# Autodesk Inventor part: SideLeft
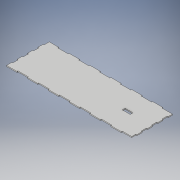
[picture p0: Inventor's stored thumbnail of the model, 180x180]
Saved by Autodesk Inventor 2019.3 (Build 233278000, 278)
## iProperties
Created: 2020-02
Part Number: SideLeft
Material: Generic
Document SubType Name: Modeling
Designer: KrystynWikoff
Density: 1 g/cm^3
Appearance: Default
Author: KrystynWikoff
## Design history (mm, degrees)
sketch "Sketch1"
  geometry: L1 (0, 0)-(304.8, 0); L2 (304.8, 0)-(304.8, -101.6); L3 (304.8, -101.6)-(0, -101.6); L4 (0, -101.6)-(0, 0)
  constraints: 8 end point, 2 parallel, 1 horizontal, 1 perpendicular
  dimensions: "d0" = 304.8 distance of L1.start L1.end; "d1" = 101.6 distance of L3.end L1.start
extrude "Extrusion1" new body sketch "Sketch1" distance "d2" = 2.3622; taper "d3" = 0 deg
sketch "Sketch2"
  geometry: L1 (-69.977, 46.99)-(-50.8, 46.99); L2 (-50.8, 46.99)-(-50.8, 53.848); L3 (-50.8, 53.848)-(-69.977, 53.848); L4 (-69.977, 53.848)-(-69.977, 46.99); L5 (0, 0)-(0, 101.6) reference; L6 (-304.8, 0)-(0, 0) reference
  constraints: 8 end point, 2 parallel, 1 horizontal, 1 perpendicular
  dimensions: "d4" = 6.858 distance of L1.end L2.end; "d5" = 19.177 distance of L2.end L3.end; "d6" = 50.8 distance between parallel lines of L5 L2; "d7" = 46.99 distance between parallel lines of L6 L1
extrude "Extrusion2" cut sketch "Sketch2" distance "d8" = 2.3622; taper "d9" = 0 deg
sketch "Sketch3" dims "d17" = 25.4
  geometry: L1 (0, 101.6)-(0, 0) reference; L2 (0, 0)-(-25.4, 0); L3 (-25.4, 0)-(-25.4, 2.362); L4 (-25.4, 2.362)-(0, 2.362); L5 (0, 2.362)-(0, 0); L6 (-50.8, 0)-(-76.2, 0); L7 (-76.2, 0)-(-76.2, 2.362); L8 (-76.2, 2.362)-(-50.8, 2.362); L9 (-50.8, 2.362)-(-50.8, 0); L10 (-101.6, 0)-(-127, 0); L11 (-127, 0)-(-127, 2.362); L12 (-127, 2.362)-(-101.6, 2.362); L13 (-101.6, 2.362)-(-101.6, 0); L14 (-152.4, 0)-(-177.8, 0); L15 (-177.8, 0)-(-177.8, 2.362); L16 (-177.8, 2.362)-(-152.4, 2.362); L17 (-152.4, 2.362)-(-152.4, 0); L18 (-203.2, 0)-(-228.6, 0); L19 (-228.6, 0)-(-228.6, 2.362); L20 (-228.6, 2.362)-(-203.2, 2.362); L21 (-203.2, 2.362)-(-203.2, 0); L22 (-254, 0)-(-279.4, 0); L23 (-279.4, 0)-(-279.4, 2.362); L24 (-279.4, 2.362)-(-254, 2.362); L25 (-254, 2.362)-(-254, 0)
  constraints: 48 end point, 2 horizontal, 2 parallel, 1 collinear, 1 perpendicular, 39 other
  dimensions: "d10" = 25.4 distance of L3.end L4.end; "d11" = 2.3622 distance of L2.end L3.end; "d14" = 50.8 distance of L3.end L7.end
extrude "Extrusion3" cut sketch "Sketch3" extent not by distance; stored distance "d19" = 2.3622; taper "d20" = 0 deg
sketch "Sketch4" dims "d28" = 25.4
  geometry: L1 (0, 0)-(-2.362, 0); L2 (-2.362, 0)-(-2.362, 12.7); L3 (-2.362, 12.7)-(0, 12.7); L4 (0, 12.7)-(0, 0); L5 (0, 25.4)-(-2.362, 25.4); L6 (-2.362, 25.4)-(-2.362, 38.1); L7 (-2.362, 38.1)-(0, 38.1); L8 (0, 38.1)-(0, 25.4); L9 (0, 50.8)-(-2.362, 50.8); L10 (-2.362, 50.8)-(-2.362, 63.5); L11 (-2.362, 63.5)-(0, 63.5); L12 (0, 63.5)-(0, 50.8); L13 (0, 76.2)-(-2.362, 76.2); L14 (-2.362, 76.2)-(-2.362, 88.9); L15 (-2.362, 88.9)-(0, 88.9); L16 (0, 88.9)-(0, 76.2); L17 (0, 101.6)-(-2.362, 101.6); L18 (-2.362, 101.6)-(-2.362, 114.3); L19 (-2.362, 114.3)-(0, 114.3); L20 (0, 114.3)-(0, 101.6)
  constraints: 40 end point, 2 parallel, 1 collinear, 1 horizontal, 1 perpendicular, 1 vertical, 31 other
  dimensions: "d21" = 12.7 distance of L1.end L2.end; "d22" = 2.3622 distance of L2.end L3.end; "d25" = 25.4 distance of L2.end L6.end
extrude "Extrusion4" cut sketch "Sketch4" distance "d30" = 2.3622; taper "d31" = 0 deg
sketch "Sketch5" dims "d40" = 25.4
  geometry: L1 (-304.8, 101.6)-(-304.8, 0) reference; L2 (-304.8, 12.7)-(-302.438, 12.7); L3 (-302.438, 12.7)-(-302.438, 25.4); L4 (-302.438, 25.4)-(-304.8, 25.4); L5 (-304.8, 25.4)-(-304.8, 12.7); L6 (-304.8, 0)-(-279.4, 0) reference; L7 (-304.8, 38.1)-(-302.438, 38.1); L8 (-302.438, 38.1)-(-302.438, 50.8); L9 (-302.438, 50.8)-(-304.8, 50.8); L10 (-304.8, 50.8)-(-304.8, 38.1); L11 (-304.8, 63.5)-(-302.438, 63.5); L12 (-302.438, 63.5)-(-302.438, 76.2); L13 (-302.438, 76.2)-(-304.8, 76.2); L14 (-304.8, 76.2)-(-304.8, 63.5); L15 (-304.8, 88.9)-(-302.438, 88.9); L16 (-302.438, 88.9)-(-302.438, 101.6); L17 (-302.438, 101.6)-(-304.8, 101.6); L18 (-304.8, 101.6)-(-304.8, 88.9); 1 further point
  constraints: 32 end point, 2 parallel, 1 horizontal, 1 perpendicular, 1 point on line, 1 vertical, 24 other
  dimensions: "d32" = 12.7 distance between parallel lines of L6 L2; "d33" = 12.7 distance of L2.end L3.end; "d34" = 2.3622 distance of L2.start L2.end; "d37" = 25.4 distance of L2.start L7.start
extrude "Extrusion5" cut sketch "Sketch5" distance "d42" = 2.3622; taper "d43" = 0 deg
sketch "Sketch6" dims "d52" = 25.4
  geometry: L1 (0, 101.6)-(-302.438, 101.6) reference; L2 (-279.4, 101.6)-(-254, 101.6); L3 (-254, 101.6)-(-254, 99.238); L4 (-254, 99.238)-(-279.4, 99.238); L5 (-279.4, 99.238)-(-279.4, 101.6); L6 (-304.8, 88.9)-(-304.8, 76.2) reference; L7 (-228.6, 101.6)-(-203.2, 101.6); L8 (-203.2, 101.6)-(-203.2, 99.238); L9 (-203.2, 99.238)-(-228.6, 99.238); L10 (-228.6, 99.238)-(-228.6, 101.6); L11 (-177.8, 101.6)-(-152.4, 101.6); L12 (-152.4, 101.6)-(-152.4, 99.238); L13 (-152.4, 99.238)-(-177.8, 99.238); L14 (-177.8, 99.238)-(-177.8, 101.6); L15 (-127, 101.6)-(-101.6, 101.6); L16 (-101.6, 101.6)-(-101.6, 99.238); L17 (-101.6, 99.238)-(-127, 99.238); L18 (-127, 99.238)-(-127, 101.6); L19 (-76.2, 101.6)-(-50.8, 101.6); L20 (-50.8, 101.6)-(-50.8, 99.238); L21 (-50.8, 99.238)-(-76.2, 99.238); L22 (-76.2, 99.238)-(-76.2, 101.6); L23 (-25.4, 101.6)-(0, 101.6); L24 (0, 101.6)-(0, 99.238); L25 (0, 99.238)-(-25.4, 99.238); L26 (-25.4, 99.238)-(-25.4, 101.6); 1 further point
  constraints: 48 end point, 2 horizontal, 2 parallel, 1 perpendicular, 1 point on line, 40 other
  dimensions: "d44" = 25.4 distance between parallel lines of L6 L5; "d45" = 25.4 distance of L3.end L4.end; "d46" = 2.3622 distance of L4.end L2.start; "d49" = 50.8 distance of L2.start L7.start
extrude "Extrusion6" cut sketch "Sketch6" distance "d54" = 25.4; taper "d55" = 0 deg
body "Solid1"
